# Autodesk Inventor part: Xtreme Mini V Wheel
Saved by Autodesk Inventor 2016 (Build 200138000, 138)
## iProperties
Created: 2016-01
Part Number: Xtreme Mini V Wheel
Material: Generic
Document SubType Name: Modeling
Designer: John
Density: 1 g/cm^3
Appearance: Default
Author: John
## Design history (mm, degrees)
feature "REVOLVE1"
body "Solid1"
